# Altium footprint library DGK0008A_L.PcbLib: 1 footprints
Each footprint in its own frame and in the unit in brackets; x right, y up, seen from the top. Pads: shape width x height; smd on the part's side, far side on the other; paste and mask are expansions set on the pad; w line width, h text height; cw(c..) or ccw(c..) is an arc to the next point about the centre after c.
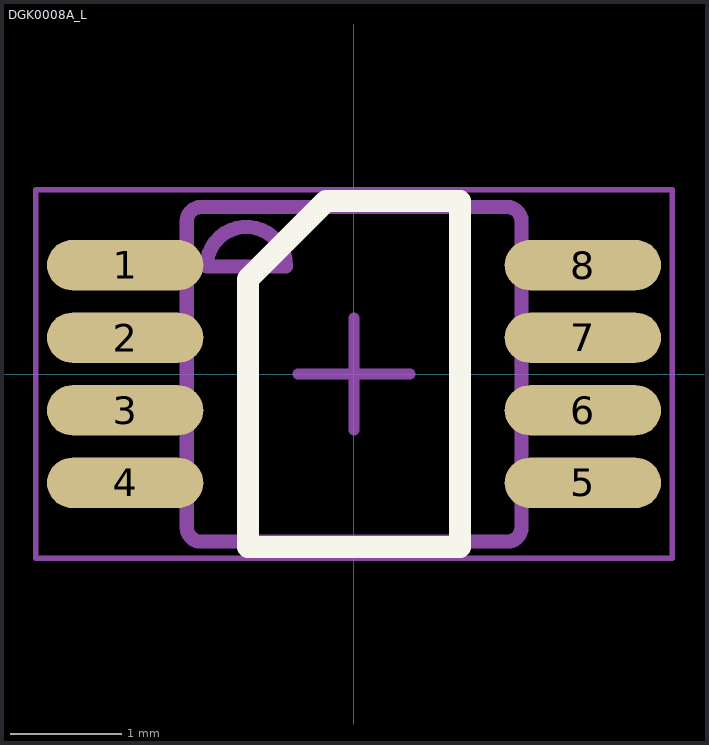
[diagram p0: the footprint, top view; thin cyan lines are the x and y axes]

## DGK0008A_L [mm] "TSOP, 8-Leads, Body 3x3mm, Pitch 0.65mm, IPC High Density"
height 1.1
pads (8):
  oval 1.4x0.45 smd mask+0.05: 1(-2.05,0.975) 2(-2.05,0.325) 3(-2.05,-0.325) 4(-2.05,-0.975) 5(2.05,-0.975) 6(2.05,-0.325) 7(2.05,0.325) 8(2.05,0.975)
Top Overlay:
  lines w0.2: -0.95,-1.55 0.95,-1.55 0.95,1.55 -0.25,1.55 -0.95,0.85 -0.95,-1.55
M5 Assembly Top:
  lines w0.127: -2.45,-1.131 -2.45,-0.826 -2.21,-0.826 -2.091,-0.826 -2.087,-0.826 -1.784,-0.826 -1.498,-0.826 -1.498,-1.131 -1.784,-1.131 -2.087,-1.131 -2.091,-1.131 -2.21,-1.131 -2.45,-1.131 ; -2.45,-0.48 -2.45,-0.175 -2.21,-0.175 -2.091,-0.175 -2.087,-0.175 -1.784,-0.175 -1.498,-0.175 -1.498,-0.48 -1.784,-0.48 -2.087,-0.48 -2.091,-0.48 -2.21,-0.48 -2.45,-0.48 ; -2.45,0.17 -2.45,0.475 -2.21,0.475 -2.091,0.475 -2.087,0.475 -1.784,0.475 -1.498,0.475 -1.498,0.17 -1.784,0.17 -2.087,0.17 -2.091,0.17 -2.21,0.17 -2.45,0.17 ; -2.45,0.82 -2.45,1.125 -2.21,1.125 -2.091,1.125 -2.087,1.125 -1.784,1.125 -1.498,1.125 -1.498,0.82 -1.784,0.82 -2.087,0.82 -2.091,0.82 -2.21,0.82 -2.45,0.82 ; -1.497,-1.377 ccw(c-1.37,-1.374) -1.373,-1.501 -1.371,-1.501 1.373,-1.501 1.375,-1.501 ccw(c1.373,-1.374) 1.5,-1.377 1.5,-1.374 1.5,1.369 1.5,1.372 ccw(c1.373,1.369) 1.375,1.496 1.373,1.496 -1.371,1.496 -1.373,1.496 ccw(c-1.37,1.369) -1.497,1.372 -1.498,1.369 -1.498,-1.374 -1.497,-1.377 ; -1.32,0.962 cw(c-0.964,0.962) -0.609,0.962 -1.32,0.962 ; 1.5,-1.131 1.786,-1.131 2.089,-1.131 2.093,-1.131 2.213,-1.131 2.452,-1.131 2.452,-0.826 2.213,-0.826 2.093,-0.826 2.089,-0.826 1.786,-0.826 1.5,-0.826 1.5,-1.131 ; 1.5,-0.48 1.786,-0.48 2.089,-0.48 2.093,-0.48 2.213,-0.48 2.452,-0.48 2.452,-0.175 2.213,-0.175 2.093,-0.175 2.089,-0.175 1.786,-0.175 1.5,-0.175 1.5,-0.48 ; 1.5,0.17 1.786,0.17 2.089,0.17 2.093,0.17 2.213,0.17 2.452,0.17 2.452,0.475 2.213,0.475 2.093,0.475 2.089,0.475 1.786,0.475 1.5,0.475 1.5,0.17 ; 1.5,0.82 1.786,0.82 2.089,0.82 2.093,0.82 2.213,0.82 2.452,0.82 2.452,1.125 2.213,1.125 2.093,1.125 2.089,1.125 1.786,1.125 1.5,1.125 1.5,0.82
  text ".Designator" at -1.15,-0.3 h0.64
M15 Courtyards Top:
  lines w0.05: -2.85,-1.65 -2.85,1.65 2.85,1.65 2.85,-1.65 -2.85,-1.65
  lines w0.1: -0.5,0 0.5,0 ; 0,-0.5 0,0.5
3D body: height 0.94, standoff -0.02, extent -2.451,-1.499 2.451,1.498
